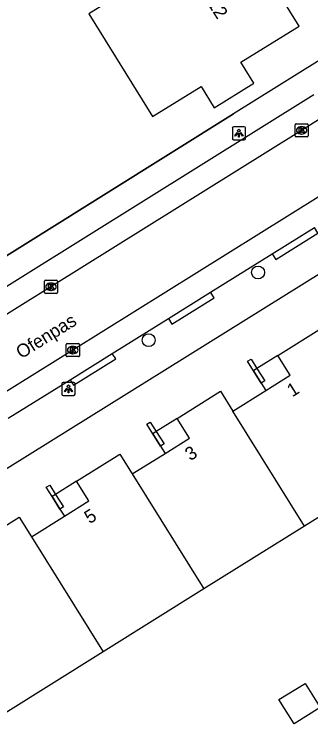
# Model space of a CAD drawing. Extents: x 158838 to 160074, y 386376 to 387776.
# Drawn here: x 159147 to 159169.5, y 387139.4 to 387193.2 of the extents above; entities that cross this region are included whole.
import ezdxf

# ---------------------------------------------------------------- set-up
doc = ezdxf.new("R2010")
doc.units = 0
for name, color, linetype in [('IMGEO_Boom', 7, 'Continuous'), ('IMGEO_Kolk', 7, 'Continuous'), ('IMGEO_Lichtpunt', 7, 'Continuous'), ('IMGEO_Muur', 7, 'Continuous'), ('IMGEO_Openbare_ruimte_label', 7, 'Continuous'), ('IMGEO_Pand', 7, 'Continuous'), ('IMGEO_Pand_nummerreeks', 7, 'Continuous'), ('IMGEO_Pand_overbouw', 7, 'Continuous'), ('IMGEO_Rijbaan_lokaal_open', 7, 'Continuous'), ('IMGEO_Voetpad_open', 7, 'Continuous')]:
    doc.layers.add(name, color=color, linetype=linetype)

msp = doc.modelspace()

# ---------------------------------------------------------------- linework, layer by layer
at = {"layer": 'IMGEO_Boom'}
for centre in [(159165.463, 387173.591), (159157.176, 387168.461)]:
    msp.add_circle(centre, 0.489, dxfattribs=at)
at = {"layer": 'IMGEO_Kolk'}
for p, q in [((159168.262, 387183.936), (159168.262, 387184.788)), ((159168.337, 387184.862), (159169.189, 387184.862)), ((159169.263, 387184.788), (159169.263, 387183.936)), ((159168.75, 387184.642), (159168.775, 387184.642)), ((159169.189, 387183.862), (159168.337, 387183.862)), ((159168.773, 387184.082), (159168.748, 387184.082)), ((159149.274, 387172.083), (159149.274, 387172.935)), ((159149.349, 387173.009), (159150.201, 387173.009)), ((159150.275, 387172.935), (159150.275, 387172.083)), ((159149.762, 387172.789), (159149.787, 387172.789)), ((159150.201, 387172.009), (159149.349, 387172.009)), ((159149.785, 387172.229), (159149.76, 387172.229)), ((159150.922, 387167.285), (159150.922, 387168.137)), ((159150.997, 387168.211), (159151.849, 387168.211)), ((159151.923, 387168.137), (159151.923, 387167.285)), ((159151.41, 387167.991), (159151.435, 387167.991)), ((159151.849, 387167.211), (159150.997, 387167.211)), ((159151.433, 387167.431), (159151.408, 387167.431))]:
    msp.add_line(p, q, dxfattribs=at)
for points in [[(159168.262, 387183.936), (159168.262, 387184.788)], [(159168.337, 387184.862), (159169.189, 387184.862)], [(159169.263, 387184.788), (159169.263, 387183.936)], [(159168.583, 387184.562), (159168.706, 387184.562), (159168.706, 387184.411), (159168.836, 387184.562), (159169, 387184.562), (159168.854, 387184.411), (159169.007, 387184.162), (159168.855, 387184.162), (159168.77, 387184.326), (159168.706, 387184.259), (159168.706, 387184.162), (159168.583, 387184.162), (159168.583, 387184.562)], [(159169.189, 387183.862), (159168.337, 387183.862)], [(159149.274, 387172.083), (159149.274, 387172.935)], [(159149.349, 387173.009), (159150.201, 387173.009)], [(159150.275, 387172.935), (159150.275, 387172.083)], [(159149.595, 387172.709), (159149.718, 387172.709), (159149.718, 387172.558), (159149.848, 387172.709), (159150.012, 387172.709), (159149.866, 387172.558), (159150.019, 387172.309), (159149.867, 387172.309), (159149.782, 387172.473), (159149.718, 387172.406), (159149.718, 387172.309), (159149.595, 387172.309), (159149.595, 387172.709)], [(159150.201, 387172.009), (159149.349, 387172.009)], [(159150.922, 387167.285), (159150.922, 387168.137)], [(159150.997, 387168.211), (159151.849, 387168.211)], [(159151.923, 387168.137), (159151.923, 387167.285)], [(159151.243, 387167.911), (159151.366, 387167.911), (159151.366, 387167.76), (159151.496, 387167.911), (159151.66, 387167.911), (159151.514, 387167.76), (159151.667, 387167.511), (159151.515, 387167.511), (159151.43, 387167.675), (159151.366, 387167.608), (159151.366, 387167.511), (159151.243, 387167.511), (159151.243, 387167.911)], [(159151.849, 387167.211), (159150.997, 387167.211)]]:
    msp.add_lwpolyline(points, dxfattribs=at)
for centre, start, end in [((159168.339, 387184.786), 91.552, 178.448), ((159168.339, 387184.786), 91.552, 178.448), ((159169.187, 387184.786), 1.552, 88.448), ((159169.187, 387184.786), 1.552, 88.448), ((159168.339, 387183.938), 181.552, 268.448), ((159168.339, 387183.938), 181.552, 268.448), ((159169.187, 387183.938), 271.552, 358.448), ((159169.187, 387183.938), 271.552, 358.448), ((159149.351, 387172.933), 91.552, 178.448), ((159149.351, 387172.933), 91.552, 178.448), ((159150.199, 387172.933), 1.552, 88.448), ((159150.199, 387172.933), 1.552, 88.448), ((159149.351, 387172.085), 181.552, 268.448), ((159149.351, 387172.085), 181.552, 268.448), ((159150.199, 387172.085), 271.552, 358.448), ((159150.199, 387172.085), 271.552, 358.448), ((159150.999, 387168.135), 91.552, 178.448), ((159150.999, 387168.135), 91.552, 178.448), ((159151.847, 387168.135), 1.552, 88.448), ((159151.847, 387168.135), 1.552, 88.448), ((159150.999, 387167.287), 181.552, 268.448), ((159150.999, 387167.287), 181.552, 268.448), ((159151.847, 387167.287), 271.552, 358.448), ((159151.847, 387167.287), 271.552, 358.448)]:
    msp.add_arc(centre, 0.0765, start, end, dxfattribs=at)
for centre, major_axis, ratio, start_param, end_param in [((159168.749, 387184.362), (-0.387, 0.002), 0.722429, 4.712389, 7.853982), ((159168.774, 387184.362), (-0.39, 0.002), 0.717154, 1.570796, 4.712389), ((159149.761, 387172.509), (-0.387, 0.002), 0.722429, 4.712389, 7.853982), ((159149.786, 387172.509), (-0.39, 0.002), 0.717154, 1.570796, 4.712389), ((159151.409, 387167.711), (-0.387, 0.002), 0.722429, 4.712389, 7.853982), ((159151.434, 387167.711), (-0.39, 0.002), 0.717154, 1.570796, 4.712389)]:
    msp.add_ellipse(centre, major_axis=major_axis, ratio=ratio, start_param=start_param, end_param=end_param, dxfattribs=at)
at = {"layer": 'IMGEO_Lichtpunt'}
for p, q in [((159163.513, 387184.543), (159163.513, 387183.736)), ((159163.513, 387184.543), (159163.513, 387183.736)), ((159164.415, 387184.638), (159163.607, 387184.638)), ((159164.415, 387184.638), (159163.607, 387184.638)), ((159164.509, 387183.736), (159164.509, 387184.543)), ((159164.509, 387183.736), (159164.509, 387184.543)), ((159163.607, 387183.642), (159164.415, 387183.642)), ((159163.607, 387183.642), (159164.415, 387183.642)), ((159150.598, 387165.168), (159150.598, 387164.361)), ((159150.598, 387165.168), (159150.598, 387164.361)), ((159151.5, 387165.263), (159150.692, 387165.263)), ((159151.5, 387165.263), (159150.692, 387165.263)), ((159151.594, 387164.361), (159151.594, 387165.168)), ((159151.594, 387164.361), (159151.594, 387165.168)), ((159150.692, 387164.267), (159151.5, 387164.267)), ((159150.692, 387164.267), (159151.5, 387164.267))]:
    msp.add_line(p, q, dxfattribs=at)
for points in [[(159163.887, 387184.207), (159163.926, 387184.179), (159163.738, 387183.917), (159163.7, 387183.944), (159163.887, 387184.207)], [(159163.989, 387184.159), (159164.036, 387184.159), (159164.036, 387183.837), (159163.989, 387183.837), (159163.989, 387184.159)], [(159164.099, 387184.179), (159164.137, 387184.206), (159164.324, 387183.944), (159164.285, 387183.916), (159164.099, 387184.179)], [(159150.972, 387164.832), (159151.011, 387164.804), (159150.823, 387164.542), (159150.785, 387164.569), (159150.972, 387164.832)], [(159151.074, 387164.784), (159151.121, 387164.784), (159151.121, 387164.462), (159151.074, 387164.462), (159151.074, 387164.784)], [(159151.184, 387164.804), (159151.222, 387164.831), (159151.409, 387164.569), (159151.37, 387164.541), (159151.184, 387164.804)]]:
    msp.add_lwpolyline(points, dxfattribs=at)
for centre in [(159164.012, 387184.341), (159151.097, 387164.966)]:
    msp.add_circle(centre, 0.0994, dxfattribs=at)
for centre, start, end in [((159163.607, 387184.543), 90, 180), ((159163.607, 387184.543), 90, 180), ((159164.415, 387184.543), 0, 90), ((159164.415, 387184.543), 0, 90), ((159163.607, 387183.736), 180, 270), ((159163.607, 387183.736), 180, 270), ((159164.415, 387183.736), 270, 0), ((159164.415, 387183.736), 270, 360), ((159150.692, 387165.168), 90, 180), ((159150.692, 387165.168), 90, 180), ((159151.5, 387165.168), 0, 90), ((159151.5, 387165.168), 0, 90), ((159150.692, 387164.361), 180, 270), ((159150.692, 387164.361), 180, 270), ((159151.5, 387164.361), 270, 0), ((159151.5, 387164.361), 270, 360)]:
    msp.add_arc(centre, 0.0946, start, end, dxfattribs=at)
at = {"layer": 'IMGEO_Muur'}
msp.add_lwpolyline([(159144.069, 387173.416), (159163.598, 387185.605)], dxfattribs=at)
at = {"layer": 'IMGEO_Pand'}
for points in [[(159154.039, 387194.052), (159152.637, 387193.187), (159157.473, 387185.404), (159161.146, 387187.686), (159162.149, 387186.072), (159165.135, 387187.931), (159164.151, 387189.525), (159168.583, 387192.261), (159166.444, 387195.705), (159164.965, 387194.785), (159163.815, 387196.599), (159162.228, 387199.102)], [(159163.545, 387163.089), (159166.048, 387164.656), (159167.902, 387165.816), (159166.968, 387167.308), (159170.261, 387169.369), (159171.188, 387167.875)], [(159165.114, 387166.148), (159164.651, 387166.865), (159164.929, 387167.022), (159165.374, 387166.311), (159165.972, 387165.38), (159165.701, 387165.21), (159165.114, 387166.148)], [(159155.923, 387158.318), (159158.418, 387159.88), (159160.272, 387161.041), (159159.338, 387162.533), (159162.613, 387164.583), (159163.545, 387163.089)], [(159168.985, 387154.372), (159163.545, 387163.089)], [(159158.346, 387160.599), (159158.074, 387160.429), (159157.484, 387161.372), (159157.026, 387162.085), (159157.296, 387162.253), (159157.745, 387161.535), (159158.346, 387160.599)], [(159148.301, 387153.547), (159150.796, 387155.109), (159152.651, 387156.271), (159151.717, 387157.762), (159154.991, 387159.812), (159155.923, 387158.318)], [(159176.61, 387159.141), (159168.985, 387154.372)], [(159155.923, 387158.318), (159161.359, 387149.602)], [(159150.454, 387155.656), (159149.862, 387156.601), (159149.403, 387157.31), (159149.675, 387157.483), (159150.124, 387156.765), (159150.725, 387155.825), (159150.454, 387155.656)], [(159140.678, 387148.777), (159143.174, 387150.339), (159145.023, 387151.496), (159144.089, 387152.989), (159147.369, 387155.042), (159148.301, 387153.547)], [(159168.985, 387154.372), (159161.359, 387149.602)], [(159148.301, 387153.547), (159153.734, 387144.832)], [(159161.359, 387149.602), (159153.734, 387144.832)], [(159153.734, 387144.832), (159146.108, 387140.062)], [(159168.19, 387139.384), (159167.046, 387141.214), (159169.026, 387142.451), (159170.169, 387140.621), (159168.19, 387139.384)]]:
    msp.add_lwpolyline(points, dxfattribs=at)
at = {"layer": 'IMGEO_Pand_overbouw'}
for points in [[(159165.374, 387166.311), (159165.114, 387166.148), (159165.701, 387165.21), (159166.048, 387164.656), (159167.902, 387165.816), (159166.968, 387167.308)], [(159157.745, 387161.535), (159157.484, 387161.372), (159158.074, 387160.429), (159158.418, 387159.88), (159160.272, 387161.041), (159159.338, 387162.533)], [(159150.124, 387156.765), (159149.862, 387156.601), (159150.454, 387155.656), (159150.796, 387155.109), (159152.651, 387156.271), (159151.717, 387157.762)]]:
    msp.add_lwpolyline(points, close=True, dxfattribs=at)
at = {"layer": 'IMGEO_Rijbaan_lokaal_open'}
for points in [[(159173.218, 387187.157), (159168.759, 387184.361), (159149.771, 387172.508), (159129.852, 387160.089), (159124.698, 387156.88)], [(159176.063, 387183.08), (159170.211, 387179.417), (159151.418, 387167.712), (159128.969, 387153.744)]]:
    msp.add_lwpolyline(points, dxfattribs=at)
at = {"layer": 'IMGEO_Voetpad_open'}
for points in [[(159171.72, 387190.674), (159163.598, 387185.605), (159144.069, 387173.416), (159142.799, 387172.623), (159132.839, 387166.407), (159124.595, 387161.262)], [(159126.365, 387160.043), (159169.681, 387187.071)], [(159177.883, 387178.311), (159177.794, 387178.26), (159131.832, 387149.649)], [(159166.541, 387174.998), (159169.734, 387176.991)], [(159166.541, 387174.998), (159166.805, 387174.574), (159169.998, 387176.567), (159169.734, 387176.991)], [(159161.863, 387172.098), (159166.541, 387174.998)], [(159158.667, 387170.104), (159161.863, 387172.098)], [(159158.667, 387170.104), (159158.931, 387169.68), (159162.127, 387171.674), (159161.863, 387172.098)], [(159154.416, 387167.461), (159158.667, 387170.104)], [(159151.219, 387165.464), (159154.416, 387167.461)], [(159151.219, 387165.464), (159151.483, 387165.04), (159154.68, 387167.037), (159154.416, 387167.461)], [(159146.528, 387162.551), (159151.219, 387165.464)]]:
    msp.add_lwpolyline(points, dxfattribs=at)

# ---------------------------------------------------------------- texts
at = {"layer": 'IMGEO_Openbare_ruimte_label'}
msp.add_text('Ofenpas', height=1, rotation=31.8778, dxfattribs=at).set_placement((159147.518, 387167.012))
at = {"layer": 'IMGEO_Pand_nummerreeks'}
for s, rotation, p in [('12', 302.3948, (159161.597, 387193.977)), ('1', 32.0398, (159168.051, 387164.115)), ('3', 32.0398, (159160.326, 387159.281)), ('5', 32.0398, (159152.697, 387154.506))]:
    msp.add_text(s, height=1, rotation=rotation, dxfattribs=at).set_placement(p)

doc.saveas('drawing.dxf')
